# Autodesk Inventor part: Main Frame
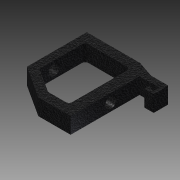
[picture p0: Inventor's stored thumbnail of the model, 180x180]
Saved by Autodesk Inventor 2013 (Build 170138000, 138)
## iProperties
Created: 2009-03
Part Number: Main Frame
Document SubType Name: Modeling
Designer: tangg
Density: 7.25 g/cm^3
Material: Cast Iron
Mass: 64.2851 g
Surface Area: 53.7917 cm^2
Volume: 8.86691 cm^3
Author: tangg
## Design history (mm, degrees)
sketch "Sketch1"
  geometry: L1 (0, 25)-(33, 25); L2 (40, 17.692)-(40, -25); L3 (40, -25)-(20, -25); L4 (0, -12.066)-(0, 25); L5 (7, 19)-(31, 19); L6 (33, 17)-(33, -17); L7 (31, -19)-(20.59, -19); L8 (5, -8.211)-(5, 17); L9 (33, 25)-(43.137, 21.604); L10 (43.137, 21.604)-(53.5, 21.604); L11 (54, 21.104)-(54, 12.914); L12 (53.5, 12.414)-(52.628, 12.414); L13 (52, 14.414)-(52, 17.692); L14 (52, 17.692)-(40, 17.692); L15 (5.914, -9.89)-(19.504, -18.679); L16 (20, -25)-(0, -12.066); L17 (48.5, 15.48)-(49.5, 15.48); L18 (50, 14.98)-(50, 14.414); L19 (48, 12.914)-(48, 14.98); L20 (50, 14.414)-(52, 14.414); L21 (52.628, 12.414)-(48.5, 12.414); A1 r 2 centre (7, 17) between (7, 19) and (5, 17); A2 r 2 centre (31, 17) between (33, 17) and (31, 19); A3 r 2 centre (31, -17) between (31, -19) and (33, -17); A4 r 2 centre (7, -8.211) between (5, -8.211) and (5.914, -9.89); A5 r 2 centre (20.59, -17) between (19.504, -18.679) and (20.59, -19); A6 r 0.5 centre (48.5, 14.98) between (48.5, 15.48) and (48, 14.98); A7 r 0.5 centre (49.5, 14.98) between (50, 14.98) and (49.5, 15.48); A8 r 0.5 centre (48.5, 12.914) between (48, 12.914) and (48.5, 12.414); A9 r 0.5 centre (53.5, 12.914) between (53.5, 12.414) and (54, 12.914); A10 r 0.5 centre (53.5, 21.104) between (54, 21.104) and (53.5, 21.604); 4 further points
  constraints: 43 end point, 20 point on circle, 20 tangent, 10 centre point, 9 parallel, 6 equal radius, 6 perpendicular, 5 point on line, 4 horizontal, 1 coincident
  dimensions: "d0" = 40 distance between parallel lines of L2 L4; "d1" = 50 distance between parallel lines of L3 L1; "d2" = 6 distance between parallel lines of L5 L1; "d3" = 6 distance between parallel lines of L3 L7; "d4" = 5 distance between parallel lines of L4 L8; "d5" = 7 distance between parallel lines of L2 L6; "d6" = 2 radius of A1; "d18" = 2 radius of A4; "d19" = 0.5 radius of A6; "d20" = 0.5 radius of A7; "d21" = 2 distance between parallel lines of L21 L20; "d22" = 2 distance between parallel lines of L18 L19; "d24" = 2 distance between parallel lines of L11 L13; "d25" = 6 distance between parallel lines of L11 L19; "d26" = 14 distance between parallel lines of L11 L2
extrude "Extrusion1" new body sketch "Sketch1" stored distance "d7" = 10; taper "d8" = 0 deg
sketch "Sketch5"
  geometry: C1 r 3.525 at (0, 0); 1 further point
  constraints: 1 centre point, 1 coincident
  dimensions: "d27" = 7.05 diameter of C1
extrude "Extrusion5" cut sketch "Sketch5" stored distance "d28" = 10; taper "d29" = 0 deg
fillet "Fillet1" dims "d15" = 1
sketch "Sketch2"
  geometry: C1 r 3.5 at (-5, 12.066); 1 further point
  constraints: 1 centre point, 1 coincident
  dimensions: "d9" = 7 diameter of C1
extrude "Extrusion2" cut sketch "Sketch2" stored distance "d10" = 8; taper "d11" = 0 deg
body "Solid1"
